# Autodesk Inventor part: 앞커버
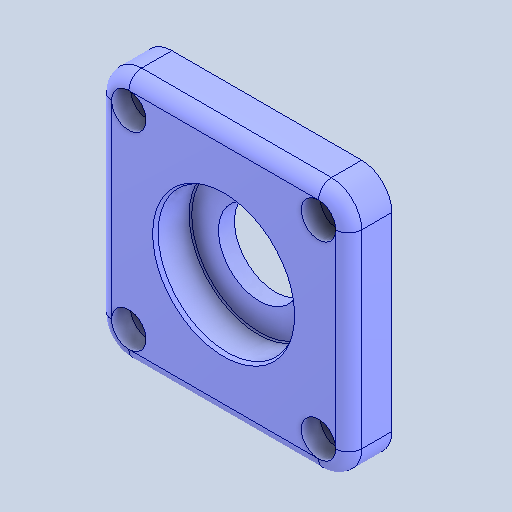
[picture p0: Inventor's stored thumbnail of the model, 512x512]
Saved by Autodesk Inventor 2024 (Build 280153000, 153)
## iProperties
Created: 2026-01
Part Number: 앞커버
Material: 알루미늄 6061
Document SubType Name: Modeling
Designer: 2-10
Density: 2.7 g/cm^3
Appearance: 기본값
Author: jhkim
Sending System: Autodesk Inventor 2026
Preprocessor: ST-DEVELOPER v20.1
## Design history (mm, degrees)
node "앞커버1"
node "솔리드2"
node "솔리드1"
